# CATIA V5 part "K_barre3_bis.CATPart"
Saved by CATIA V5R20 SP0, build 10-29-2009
Part number: barre_3_bis
Bounding box of the stored display mesh (mm): x -16.016 to -11.016, y -3 to -2, z -9.006 to 45.994
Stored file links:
  G:\Khaled_CFAO_2011\ST2M\ST2M_GR2\gcausse\Khaled\CAD_ThinkMotion\K_barre3_bis.CATPart
  C:\Documents and Settings\gcausse\Bureau\video thinkmotio\assemblage_gcausse\pupitre_think.CATProduct
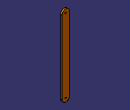
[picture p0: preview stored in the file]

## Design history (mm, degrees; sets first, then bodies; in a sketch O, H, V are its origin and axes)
Set1
  Sketch1 on Plane1, origin (0, -2, 0), H (-1, 0, 0), V (0, 0, 1)
    line L1 (11.0157, 43.4941) -> (11.0157, -6.5059)
    arc A1 centre (13.5157, -6.5059) radius 2.5 from (11.0157, -6.5059) to (16.0157, -6.5059) ccw
    point P3 (13.5157, -6.5059)
    line L2 (16.0157, -6.5059) -> (16.0157, 43.4941)
    arc A2 centre (13.5157, 43.4941) radius 2.5 from (16.0157, 43.4941) to (11.0157, 43.4941) ccw
    point P6 (13.5157, 43.4941)
    reference projected point E1 (13.5157, 43.4941) from Point2
    reference projected point E2 (13.5157, -6.5059) from Point3
    distance L2 L1 = 5
    tangency: A1 L1, A2 L2, L1 A2, L2 A1
    coincidence: P6 E1, P3 E2
  Point1: stored without definition
Set2
  Plane1: linked copy from another document
  Point2: linked copy from another document
  Point3: linked copy from another document
Body1 (main body)
  Pad1: profile Sketch1, direction (0, -1, 0), length 1
  Sketch2 on start face of Pad1, origin (-14.4845, -2, 41.4892), H (1, 0, 0), V (0, 0, -1)
    point P1 (0.9689, -2.0049)
    reference projected point E1 (0.9689, -2.0049) from Point2
    coincidence: P1 E1
  Hole1: placed by Sketch2, at (-13.5157, -2, 43.4941) direction (0, -1, 0), diameter 1, depth 1
  Sketch3 on start face of Pad1, origin (-14.6299, -2, -4.6039), H (1, 0, 0), V (0, 0, -1)
    point P1 (1.1142, 1.9021)
    reference projected point E1 (1.1142, 1.9021) from Point3
    coincidence: E1 P1
  Hole2: placed by Sketch3, at (-13.5157, -2, -6.5059) direction (0, -1, 0), diameter 1, depth 1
